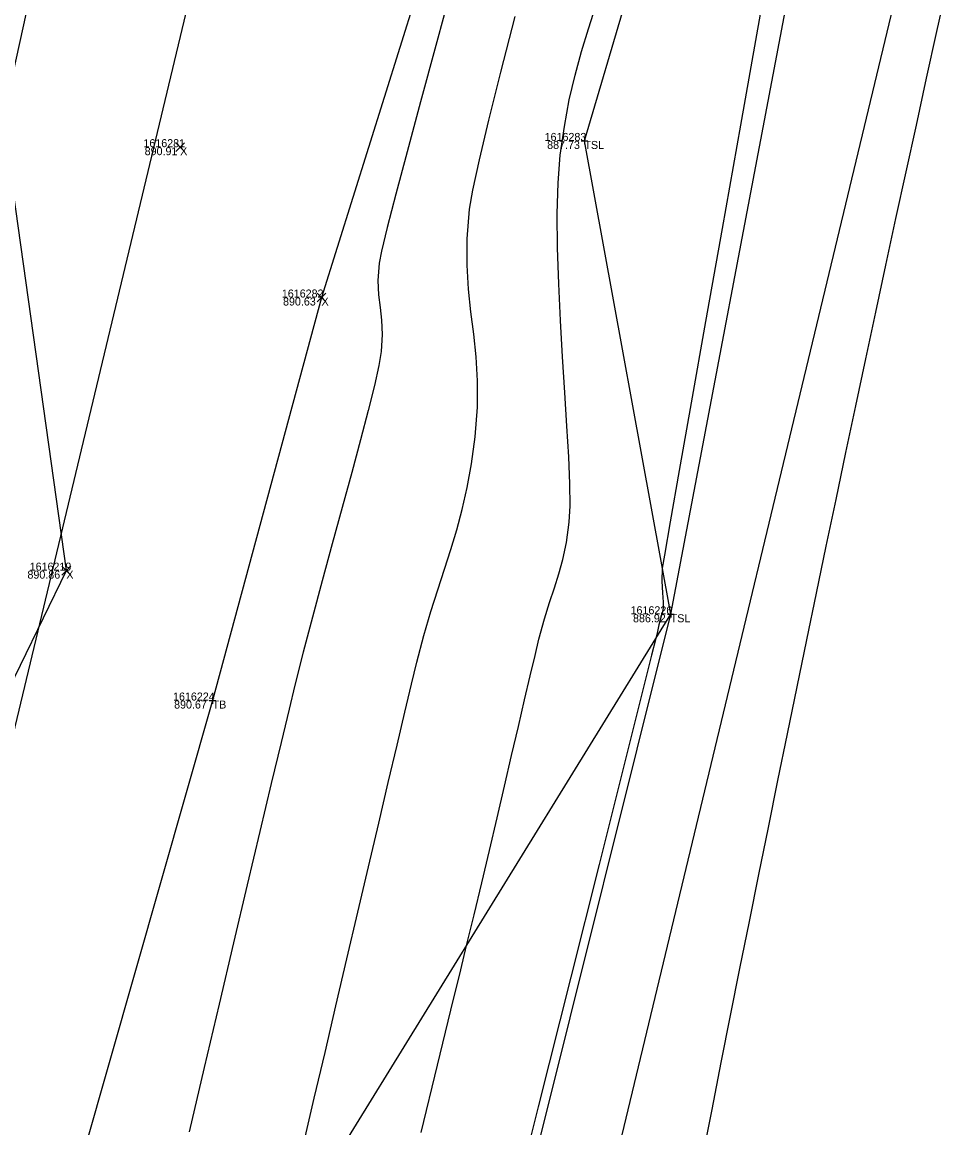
# Model space of a CAD drawing. Extents: x 1957117 to 1971063, y 701601 to 715861.
# Drawn here: x 1963332.78 to 1963373.56, y 706062.39 to 706110.73 of the extents above; entities that cross this region are included whole.
import ezdxf

# ---------------------------------------------------------------- set-up
doc = ezdxf.new("R2010")
doc.units = 0
for name, color, linetype in [('AP_X_Lights', 7, 'Continuous'), ('DT_X_Break_Line', 7, 'Continuous'), ('DT_X_Contour_Major', 7, 'Continuous'), ('DT_X_Contour_Minor', 7, 'Continuous'), ('DT_X_TIN_Hull', 7, 'Continuous'), ('GE_X_CL_20', 7, 'Continuous'), ('HY_X_Water_Edge', 7, 'Continuous'), ('PV_P_Drive', 7, 'Continuous'), ('PV_P_Shoulder', 7, 'Continuous'), ('RS_Raster1', 7, 'Continuous'), ('RW_X_Esmt_RR', 7, 'Continuous'), ('SC_Scratch1', 7, 'Continuous'), ('SC_Shading5', 7, 'Continuous')]:
    doc.layers.add(name, color=color, linetype=linetype)

msp = doc.modelspace()

# ---------------------------------------------------------------- linework, layer by layer
at = {"layer": 'AP_X_Lights'}
for p, q in [((1963339.499, 706105.067), (1963339.887, 706105.457)), ((1963339.499, 706105.457), (1963339.887, 706105.067)), ((1963345.68, 706098.495), (1963346.068, 706098.885)), ((1963345.68, 706098.885), (1963346.068, 706098.495)), ((1963334.523, 706086.555), (1963334.911, 706086.945)), ((1963334.523, 706086.945), (1963334.911, 706086.555))]:
    msp.add_line(p, q, dxfattribs=at)
at = {"layer": 'DT_X_Break_Line'}
for points in [[(1963248.355, 705747.376), (1963261.829, 705795.923), (1963267.581, 705840.559), (1963287.153, 705892.264), (1963291.083, 705944.763), (1963301.574, 705996.211), (1963311.528, 706039.027), (1963334.717, 706086.75), (1963331.957, 706106.508), (1963348.786, 706182.796), (1963365.664, 706223.934), (1963373.462, 706281.461), (1963387.853, 706330.217), (1963397.264, 706379.501), (1963407.696, 706427.592), (1963426.755, 706477.16), (1963442.136, 706524.014), (1963446.007, 706569.971), (1963489.391, 706666.839), (1963500.526, 706701.536)], [(1963509.92, 706697.686), (1963502.832, 706666.547), (1963464.625, 706568.104), (1963439.113, 706472.593), (1963428.782, 706425.675), (1963415.739, 706378.185), (1963398.991, 706327.191), (1963392.393, 706279.173), (1963377.9, 706227.719), (1963369.87, 706175.335), (1963345.874, 706098.69), (1963341.112, 706081.071), (1963328.328, 706036.261), (1963311.276, 705989.111), (1963300.503, 705940.076), (1963293.199, 705890.767), (1963276.592, 705844.792), (1963268.336, 705791.927), (1963260.722, 705745.719)], [(1963274.602, 705735.973), (1963292.982, 705784.032), (1963302.841, 705839.645), (1963309.732, 705887.345), (1963317.684, 705934.969), (1963334.587, 705978.262), (1963333.365, 706039.768), (1963361.138, 706084.843), (1963357.365, 706105.535), (1963378.943, 706178.629), (1963396.437, 706235.152), (1963403.946, 706276.884), (1963413.88, 706328.936), (1963427.392, 706367.127), (1963440.399, 706419.945), (1963448.239, 706464.72), (1963530.121, 706695.075)]]:
    msp.add_lwpolyline(points, dxfattribs=at)
at = {"layer": 'DT_X_Contour_Major'}
msp.add_lwpolyline([(1963351.603, 706112.402), (1963350.872, 706109.714), (1963350.205, 706107.251), (1963349.618, 706105.065), (1963349.126, 706103.212), (1963348.747, 706101.745), (1963348.495, 706100.718), (1963348.386, 706100.186), (1963348.338, 706099.432), (1963348.365, 706098.811), (1963348.432, 706098.256), (1963348.498, 706097.702), (1963348.527, 706097.08), (1963348.48, 706096.326), (1963348.377, 706095.719), (1963348.182, 706094.847), (1963347.909, 706093.749), (1963347.575, 706092.467), (1963347.192, 706091.042), (1963346.777, 706089.513), (1963346.342, 706087.922), (1963345.903, 706086.309), (1963345.475, 706084.716), (1963345.072, 706083.182), (1963344.708, 706081.748), (1963344.452, 706080.695), (1963344.103, 706079.243), (1963343.674, 706077.444), (1963343.178, 706075.349), (1963342.625, 706073.008), (1963342.027, 706070.473), (1963341.397, 706067.796), (1963340.746, 706065.026), (1963340.085, 706062.216)], dxfattribs=at)
msp.add_lwpolyline([(1963351.603, 706112.402), (1963350.872, 706109.714), (1963350.205, 706107.251), (1963349.618, 706105.065), (1963349.126, 706103.212), (1963348.747, 706101.745), (1963348.495, 706100.718), (1963348.386, 706100.186), (1963348.338, 706099.432), (1963348.365, 706098.811), (1963348.432, 706098.256), (1963348.498, 706097.702), (1963348.527, 706097.08), (1963348.48, 706096.326), (1963348.377, 706095.719), (1963348.182, 706094.847), (1963347.909, 706093.749), (1963347.575, 706092.467), (1963347.192, 706091.042), (1963346.777, 706089.513), (1963346.342, 706087.922), (1963345.903, 706086.309), (1963345.475, 706084.716), (1963345.072, 706083.182), (1963344.708, 706081.748), (1963344.452, 706080.695), (1963344.103, 706079.243), (1963343.674, 706077.444), (1963343.178, 706075.349), (1963342.625, 706073.008), (1963342.027, 706070.473), (1963341.397, 706067.796), (1963340.746, 706065.026), (1963340.085, 706062.216)], dxfattribs=at)
at = {"layer": 'DT_X_Contour_Minor'}
for points in [[(1963350.234, 706062.181), (1963350.95, 706065.135), (1963351.53, 706067.533), (1963351.958, 706069.3), (1963352.217, 706070.364), (1963352.542, 706071.708), (1963352.875, 706073.101), (1963353.211, 706074.52), (1963353.544, 706075.938), (1963353.869, 706077.331), (1963354.182, 706078.674), (1963354.477, 706079.941), (1963354.75, 706081.109), (1963354.994, 706082.151), (1963355.206, 706083.042), (1963355.38, 706083.759), (1963355.617, 706084.637), (1963355.842, 706085.363), (1963356.054, 706085.998), (1963356.248, 706086.605), (1963356.423, 706087.244), (1963356.575, 706087.977), (1963356.702, 706088.867), (1963356.74, 706089.582), (1963356.729, 706090.548), (1963356.68, 706091.724), (1963356.603, 706093.067), (1963356.51, 706094.537), (1963356.411, 706096.092), (1963356.317, 706097.692), (1963356.24, 706099.294), (1963356.19, 706100.858), (1963356.178, 706102.343), (1963356.214, 706103.706), (1963356.311, 706104.907), (1963356.488, 706106.173), (1963356.705, 706107.333), (1963356.955, 706108.414), (1963357.235, 706109.441), (1963357.537, 706110.439), (1963357.859, 706111.436)], [(1963350.234, 706062.181), (1963350.95, 706065.135), (1963351.53, 706067.533), (1963351.958, 706069.3), (1963352.217, 706070.364), (1963352.542, 706071.708), (1963352.875, 706073.101), (1963353.211, 706074.52), (1963353.544, 706075.938), (1963353.869, 706077.331), (1963354.182, 706078.674), (1963354.477, 706079.941), (1963354.75, 706081.109), (1963354.994, 706082.151), (1963355.206, 706083.042), (1963355.38, 706083.759), (1963355.617, 706084.637), (1963355.842, 706085.363), (1963356.054, 706085.998), (1963356.248, 706086.605), (1963356.423, 706087.244), (1963356.575, 706087.977), (1963356.702, 706088.867), (1963356.74, 706089.582), (1963356.729, 706090.548), (1963356.68, 706091.724), (1963356.603, 706093.067), (1963356.51, 706094.537), (1963356.411, 706096.092), (1963356.317, 706097.692), (1963356.24, 706099.294), (1963356.19, 706100.858), (1963356.178, 706102.343), (1963356.214, 706103.706), (1963356.311, 706104.907), (1963356.488, 706106.173), (1963356.705, 706107.333), (1963356.955, 706108.414), (1963357.235, 706109.441), (1963357.537, 706110.439), (1963357.859, 706111.436)], [(1963345.11, 706061.794), (1963345.558, 706063.696), (1963346.026, 706065.683), (1963346.503, 706067.722), (1963346.985, 706069.779), (1963347.461, 706071.818), (1963347.926, 706073.807), (1963348.372, 706075.71), (1963348.791, 706077.495), (1963349.175, 706079.125), (1963349.517, 706080.568), (1963349.809, 706081.789), (1963350.044, 706082.753), (1963350.351, 706083.92), (1963350.656, 706084.964), (1963350.955, 706085.917), (1963351.245, 706086.809), (1963351.522, 706087.67), (1963351.783, 706088.532), (1963352.024, 706089.425), (1963352.242, 706090.379), (1963352.432, 706091.426), (1963352.591, 706092.596), (1963352.692, 706093.891), (1963352.696, 706095.045), (1963352.632, 706096.096), (1963352.526, 706097.087), (1963352.406, 706098.058), (1963352.301, 706099.049), (1963352.238, 706100.1), (1963352.244, 706101.253), (1963352.349, 706102.547), (1963352.493, 706103.389), (1963352.777, 706104.702), (1963353.188, 706106.437), (1963353.711, 706108.546), (1963354.332, 706110.982)], [(1963345.11, 706061.794), (1963345.558, 706063.696), (1963346.026, 706065.683), (1963346.503, 706067.722), (1963346.985, 706069.779), (1963347.461, 706071.818), (1963347.926, 706073.807), (1963348.372, 706075.71), (1963348.791, 706077.495), (1963349.175, 706079.125), (1963349.517, 706080.568), (1963349.809, 706081.789), (1963350.044, 706082.753), (1963350.351, 706083.92), (1963350.656, 706084.964), (1963350.955, 706085.917), (1963351.245, 706086.809), (1963351.522, 706087.67), (1963351.783, 706088.532), (1963352.024, 706089.425), (1963352.242, 706090.379), (1963352.432, 706091.426), (1963352.591, 706092.596), (1963352.692, 706093.891), (1963352.696, 706095.045), (1963352.632, 706096.096), (1963352.526, 706097.087), (1963352.406, 706098.058), (1963352.301, 706099.049), (1963352.238, 706100.1), (1963352.244, 706101.253), (1963352.349, 706102.547), (1963352.493, 706103.389), (1963352.777, 706104.702), (1963353.188, 706106.437), (1963353.711, 706108.546), (1963354.332, 706110.982)], [(1963365.053, 706111.072), (1963364.187, 706106.221), (1963363.383, 706101.713), (1963362.659, 706097.636), (1963362.028, 706094.079), (1963361.509, 706091.133), (1963361.115, 706088.887), (1963360.864, 706087.431), (1963360.771, 706086.854), (1963360.756, 706086.29), (1963360.778, 706085.775), (1963360.807, 706085.371), (1963360.813, 706085.138), (1963360.773, 706084.95), (1963360.716, 706084.764), (1963360.678, 706084.601), (1963360.625, 706084.374), (1963360.56, 706084.096), (1963360.485, 706083.783), (1963360.302, 706083.053), (1963359.806, 706081.076), (1963359.03, 706077.983), (1963358.007, 706073.905), (1963356.769, 706068.972), (1963355.349, 706063.316), (1963353.78, 706057.068)], [(1963365.053, 706111.072), (1963364.187, 706106.221), (1963363.383, 706101.713), (1963362.659, 706097.636), (1963362.028, 706094.079), (1963361.509, 706091.133), (1963361.115, 706088.887), (1963360.864, 706087.431), (1963360.771, 706086.854), (1963360.756, 706086.29), (1963360.778, 706085.775), (1963360.807, 706085.371), (1963360.813, 706085.138), (1963360.773, 706084.95), (1963360.716, 706084.764), (1963360.678, 706084.601), (1963360.625, 706084.374), (1963360.56, 706084.096), (1963360.485, 706083.783), (1963360.302, 706083.053), (1963359.806, 706081.076), (1963359.03, 706077.983), (1963358.007, 706073.905), (1963356.769, 706068.972), (1963355.349, 706063.316), (1963353.78, 706057.068)]]:
    msp.add_lwpolyline(points, dxfattribs=at)
at = {"layer": 'DT_X_TIN_Hull'}
msp.add_lwpolyline([(1963309.732, 705887.345), (1963335.126, 705936.766), (1963334.587, 705978.262), (1963361.138, 706084.843), (1963378.943, 706178.629), (1963396.437, 706235.152), (1963403.946, 706276.884), (1963413.88, 706328.936), (1963427.392, 706367.127), (1963440.399, 706419.945), (1963448.239, 706464.72), (1963464.625, 706568.104)], dxfattribs=at)
at = {"layer": 'GE_X_CL_20'}
msp.add_lwpolyline([(1963418.3, 706437.397), (1962895.621, 704261.062)], dxfattribs=at)
at = {"layer": 'HY_X_Water_Edge'}
msp.add_spline([(1963191.723, 701994.048), (1963062.047, 702441.167), (1962863.491, 703169.356), (1962827.53, 703438.691), (1962823.213, 703537.412), (1962817.962, 703593.874), (1962817.97, 703697.316), (1962828.582, 703804.235), (1962836.461, 703844.734), (1962850.687, 703896.004), (1962867.251, 703938.846), (1962873.848, 703992.355), (1962884.135, 704091.371), (1962891.241, 704140.854), (1962897.382, 704180.529), (1962905.467, 704230.979), (1962943.949, 704328.022), (1962948.537, 704378.842), (1962964.114, 704426.264), (1963004.885, 704570.73), (1963042.054, 704716.522), (1963062.038, 704814.417), (1963072.171, 704860.237), (1963090.023, 704956.798), (1963107.066, 705031.783), (1963133.773, 705105.742), (1963148.685, 705206.74), (1963175.48, 705301.059), (1963191.635, 705353.417), (1963210.988, 705447.286), (1963219.532, 705497.27), (1963230.124, 705549.475), (1963251.052, 705591.159), (1963275.289, 705693.429), (1963292.982, 705784.032), (1963302.841, 705839.645), (1963335.126, 705936.766), (1963359.752, 706046.75), (1963389.133, 706177.299), (1963417.827, 706273.456), (1963475.868, 706451.902), (1963533.782, 706640.53), (1963553.86, 706696.984), (1963580.184, 706715.425), (1963609.172, 706718.73), (1963617.062, 706714.691), (1963619.447, 706694.678), (1963564.282, 706533.07), (1963531.853, 706395.229), (1963434.4, 706006.96), (1963354.09, 705679.186), (1963237.513, 705206.07), (1963167.369, 704892.962), (1963059.145, 704434.176), (1962907.914, 703908.742), (1962877.458, 703703.326), (1962898.357, 703412.121), (1962942.65, 703052.267), (1963048.963, 702674.866), (1963191.468, 702189.666), (1963245.396, 702019.832)], degree=3, dxfattribs=at)
at = {"layer": 'PV_P_Drive'}
for p, q in [((1963357.219, 706105.535), (1963357.511, 706105.535)), ((1963357.365, 706105.681), (1963357.365, 706105.389)), ((1963357.365, 706105.535), (1963357.365, 706105.535)), ((1963360.992, 706084.843), (1963361.284, 706084.843)), ((1963361.138, 706084.989), (1963361.138, 706084.697)), ((1963361.138, 706084.843), (1963361.138, 706084.843)), ((1963341.112, 706081.217), (1963341.112, 706080.925)), ((1963340.966, 706081.071), (1963341.258, 706081.071)), ((1963341.112, 706081.071), (1963341.112, 706081.071))]:
    msp.add_line(p, q, dxfattribs=at)
at = {"layer": 'RW_X_Esmt_RR'}
msp.add_line((1962924.791, 704254.057), (1963447.47, 706430.392), dxfattribs=at)
at = {"layer": 'SC_Shading5'}
for points in [[(1963026.912, 704294.121), (1963138.818, 704737.794), (1963251.679, 705213.963), (1963374.306, 705730.111), (1963454.783, 706045.593), (1963517.244, 706296.713), (1963562.763, 706479.256), (1963580.13, 706553.799), (1963589.678, 706586.994)], [(1963609.915, 706579.703), (1963587.283, 706499.153), (1963552.056, 706354.005), (1963480.911, 706069.234), (1963357.401, 705576.869), (1963272.751, 705226.931), (1963210.247, 704956.481), (1963044.97, 704288.881)]]:
    msp.add_spline(points, degree=3, dxfattribs=at)

# ---------------------------------------------------------------- texts
at = {"layer": 'PV_P_Shoulder'}
for s, p in [('887.73', (1963355.736, 706105.185)), ('890.91', (1963338.141, 706104.912)), ('890.63', (1963344.19, 706098.34)), ('890.86', (1963333.017, 706086.4)), ('886.92', (1963359.49, 706084.493)), ('890.67', (1963339.428, 706080.721))]:
    msp.add_text(s, height=0.35, dxfattribs=at).set_placement(p)
at = {"layer": 'RS_Raster1'}
for s, p in [('1616283', (1963355.626, 706105.535)), ('1616281', (1963338.086, 706105.262)), ('1616282', (1963344.138, 706098.69)), ('1616219', (1963333.114, 706086.75)), ('1616226', (1963359.383, 706084.843)), ('1616224', (1963339.382, 706081.071))]:
    msp.add_text(s, height=0.35, dxfattribs=at).set_placement(p)
at = {"layer": 'SC_Scratch1'}
for s, p in [('TSL', (1963357.365, 706105.185)), ('X', (1963339.693, 706104.912)), ('X', (1963345.874, 706098.34)), ('X', (1963334.717, 706086.4)), ('TSL', (1963361.138, 706084.493)), ('TB', (1963341.112, 706080.721))]:
    msp.add_text(s, height=0.35, dxfattribs=at).set_placement(p)

doc.saveas('drawing.dxf')
